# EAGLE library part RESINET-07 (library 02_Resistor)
Resistor Network(7) 7 peaces
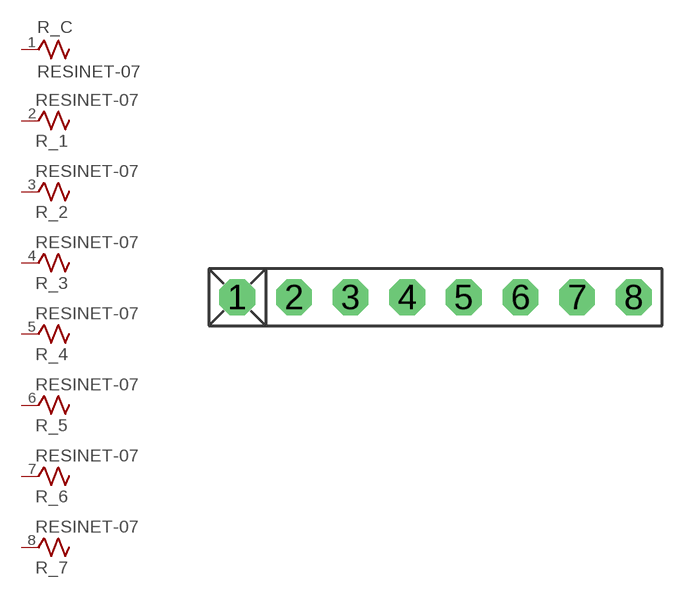
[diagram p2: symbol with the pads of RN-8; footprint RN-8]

Designator prefix R; gates _C=RESINET-COM _1=RESINET-X _2=RESINET-X _3=RESINET-X _4=RESINET-X _5=RESINET-X _6=RESINET-X _7=RESINET-X

## RESINET-07  [RN-8]
1  _C:1  pas
2  _1:1  pas
3  _2:1  pas
4  _3:1  pas
5  _4:1  pas
6  _5:1  pas
7  _6:1  pas
8  _7:1  pas

## Footprint RN-8 (pad centres in mm)
Resistor Network(7) 7 peaces
drill 0.813 pad 1.6 octagon: 1 -8.89,0; 2 -6.35,0; 3 -3.81,0; 4 -1.27,0; 5 1.27,0; 6 3.81,0; 7 6.35,0; 8 8.89,0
